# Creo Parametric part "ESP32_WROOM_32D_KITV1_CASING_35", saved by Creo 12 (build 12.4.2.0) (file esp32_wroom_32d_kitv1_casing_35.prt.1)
Units: Custom; MM, KILOGRAM, SECS

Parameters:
  PTC_WM_ITERATION = "0"
  PTC_WM_VERSION = "-.0"
  PTC_WM_LIFECYCLE_STATE = "In Work"
  PTC_WM_LIFECYCLE = "MO_CADDocument"
  PTC_WM_CREATED_BY = "Maximilian Roepper (Z0017RMS: MO)"
  PTC_WM_CREATED_ON = "18-Sep-26 11:36:42 AM"
  PTC_WM_MODIFIED_BY = "Maximilian Roepper (Z0017RMS: MO)"
  PTC_WM_MODIFIED_ON = "18-Sep-26 11:36:46 AM"
  PDMLINKNUMBER = "PDM000071455340"
  PTC_WM_NAME = "esp32_wroom_32d_kitv1_casing_35.prt"
  PTC_WM_NUMBER = "PDM000071455340"

Other parameters: WEIGHT, WEIGHT_FACTOR, WEIGHT_ADD, _MASS_TEMP, _DIFF_TEMP, MC_ERRORS, SUPPLIER

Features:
  1. coordinate system
  2. datum plane "PRT_YZ"
  3. datum plane "PRT_XY"
  4. datum plane "PRT_XZ"
  5. coordinate system
  6. datum axis
  7. datum axis
  8. datum axis
  9. coordinate system
  10. imported feature
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
Other named items: PRT, SIEMENS_MO, DRW_VIEW_ORG, PRT_X, PRT_Y, PRT_Z, CS0, ROUGH_GROB

Layers: 00_STD_CSYS-KSYS, 01_STD_PLANES-EBENEN, 02_STD_AXES-ACHSEN, 03_STD_CSYS-KSYS, 24_IMPORT_FEAT-IMPORT_KE

Surfaces: 5 plane, 1 cylinder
